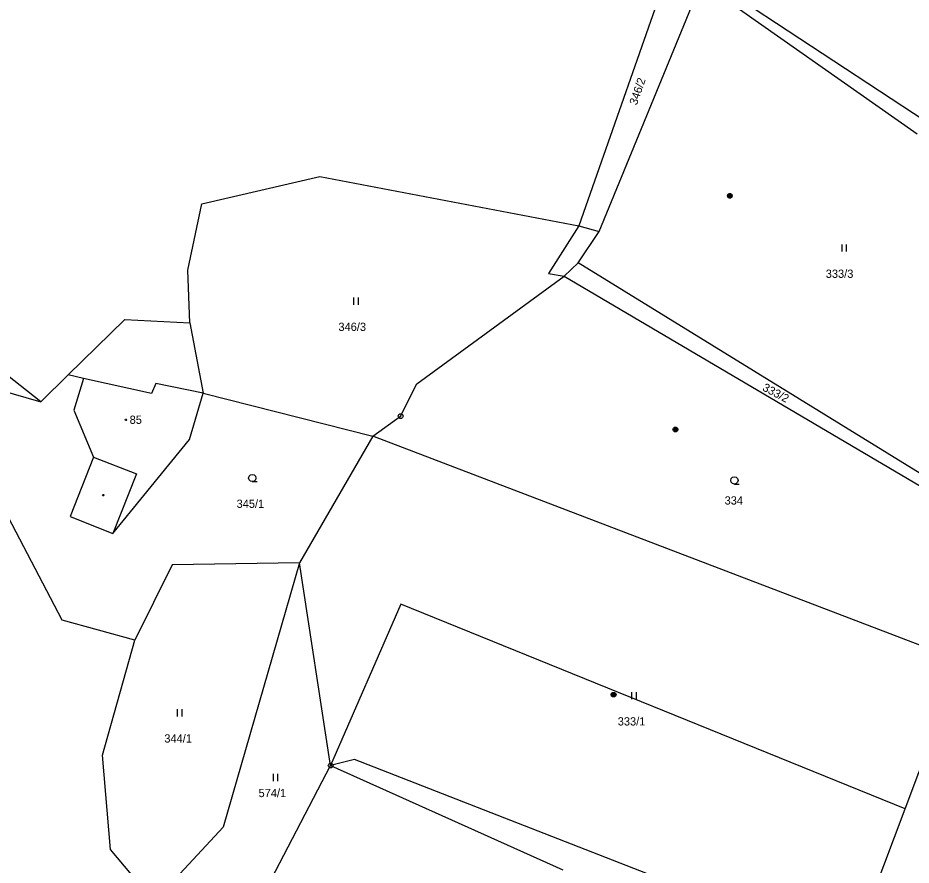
# Model space of a CAD drawing. Extents: x -694465 to -690527, y -983694 to -978978.
# Drawn here: x -692625.8 to -692441.8, y -981604.7 to -981430.2 of the extents above; entities that cross this region are included whole.
import ezdxf

# ---------------------------------------------------------------- set-up
doc = ezdxf.new("R2010")
doc.units = 0
for name, color, linetype in [('Vrstva 1', 7, 'Continuous'), ('Vrstva 18', 7, 'Continuous'), ('Vrstva 19', 7, 'Continuous'), ('Vrstva 24', 7, 'Continuous'), ('Vrstva 25', 7, 'Continuous'), ('Vrstva 26', 7, 'Continuous')]:
    doc.layers.add(name, color=color, linetype=linetype)

msp = doc.modelspace()

# ---------------------------------------------------------------- linework, layer by layer
at = {"layer": 'Vrstva 1'}
for points in [[(-692490.44, -981416.36), (-692510.29, -981472.97)], [(-692506.12, -981474.15), (-692485.04, -981422.83)], [(-692485.04, -981422.83), (-692440.58, -981454.06)], [(-692438.95, -981451.45), (-692476.57, -981426.72)], [(-692587.95, -981468.48), (-692563.64, -981462.84)], [(-692563.64, -981462.84), (-692510.29, -981472.97)], [(-692590.86, -981482.14), (-692587.95, -981468.48)], [(-692621.12, -981509.23), (-692665.4, -981474.33)], [(-692510.29, -981472.97), (-692516.53, -981482.79)], [(-692510.4, -981480.6), (-692506.12, -981474.15)], [(-692510.29, -981472.97), (-692506.12, -981474.15)], [(-692510.4, -981480.6), (-692513.28, -981483.34)], [(-692428.7, -981530.97), (-692510.4, -981480.6)], [(-692590.43, -981492.99), (-692590.86, -981482.14)], [(-692543.67, -981505.54), (-692513.28, -981483.34)], [(-692516.53, -981482.79), (-692513.28, -981483.34)], [(-692513.28, -981483.34), (-692428.36, -981533.41)], [(-692615.475, -981503.709), (-692603.78, -981492.27)], [(-692603.78, -981492.27), (-692590.43, -981492.99)], [(-692590.43, -981492.99), (-692587.69, -981507.45)], [(-692621.12, -981509.23), (-692615.475, -981503.709)], [(-692612.35, -981504.49), (-692615.475, -981503.709)], [(-692635.66, -981505.07), (-692621.12, -981509.23)], [(-692612.35, -981504.49), (-692614.34, -981511)], [(-692598.29, -981507.58), (-692612.35, -981504.49)], [(-692597.42, -981505.47), (-692598.29, -981507.58)], [(-692587.69, -981507.45), (-692597.42, -981505.47)], [(-692546.99, -981512.2), (-692543.67, -981505.54)], [(-692590.47, -981517.03), (-692587.69, -981507.45)], [(-692587.69, -981507.45), (-692552.71, -981516.36)], [(-692614.34, -981511), (-692610.29, -981520.64)], [(-692616.72, -981554.28), (-692638.99, -981511.81)], [(-692552.71, -981516.36), (-692546.99, -981512.2)], [(-692552.71, -981516.36), (-692567.81, -981542.46)], [(-692431.57, -981562.6), (-692552.71, -981516.36)], [(-692606.26, -981536.37), (-692590.47, -981517.03)], [(-692610.29, -981520.64), (-692615.1, -981532.9)], [(-692610.29, -981520.64), (-692601.44, -981524.11)], [(-692601.44, -981524.11), (-692606.26, -981536.37)], [(-692615.1, -981532.9), (-692606.26, -981536.37)], [(-692567.81, -981542.46), (-692594.07, -981542.83)], [(-692567.81, -981542.46), (-692583.58, -981596.88)], [(-692561.41, -981584.19), (-692567.81, -981542.46)], [(-692594.07, -981542.83), (-692601.73, -981558.39)], [(-692443.06, -981593.114), (-692546.953, -981550.948), (-692561.41, -981584.19)], [(-692601.73, -981558.39), (-692616.72, -981554.28)], [(-692608.43, -981582.04), (-692601.73, -981558.39)], [(-692443.06, -981593.114), (-692431.57, -981562.6)], [(-692606.77, -981601.48), (-692608.43, -981582.04)], [(-692556.51, -981582.94), (-692561.41, -981584.19)], [(-692454.26, -981622.86), (-692556.51, -981582.94)], [(-692582.39, -981624.43), (-692561.41, -981584.19)], [(-692561.41, -981584.19), (-692513.61, -981605.72)], [(-692454.26, -981622.86), (-692443.06, -981593.114)], [(-692583.58, -981596.88), (-692597.76, -981612.22)], [(-692597.76, -981612.22), (-692606.77, -981601.48)]]:
    msp.add_lwpolyline(points, dxfattribs=at)
at = {"layer": 'Vrstva 24'}
for points in [[(-692546.836, -981511.724), (-692546.586, -981511.906), (-692546.49, -981512.2), (-692546.586, -981512.494), (-692546.836, -981512.676), (-692547.144, -981512.676), (-692547.394, -981512.494), (-692547.49, -981512.2), (-692547.394, -981511.906), (-692547.144, -981511.724)], [(-692561.256, -981583.714), (-692561.006, -981583.896), (-692560.91, -981584.19), (-692561.006, -981584.484), (-692561.256, -981584.666), (-692561.564, -981584.666), (-692561.814, -981584.484), (-692561.91, -981584.19), (-692561.814, -981583.896), (-692561.564, -981583.714)], [(-692561.256, -981583.714), (-692561.006, -981583.896), (-692560.91, -981584.19), (-692561.006, -981584.484), (-692561.256, -981584.666), (-692561.564, -981584.666), (-692561.814, -981584.484), (-692561.91, -981584.19), (-692561.814, -981583.896), (-692561.564, -981583.714)]]:
    msp.add_lwpolyline(points, close=True, dxfattribs=at)
for points in [[(-692547.109, -981512.2), (-692546.87, -981512.2)], [(-692561.529, -981584.19), (-692561.29, -981584.19)], [(-692561.529, -981584.19), (-692561.29, -981584.19)]]:
    msp.add_lwpolyline(points, dxfattribs=at)
at = {"layer": 'Vrstva 25'}
for points in [[(-692456.13, -981476.82), (-692456.13, -981478.32)], [(-692455.13, -981478.32), (-692455.13, -981476.82)], [(-692556.7, -981487.76), (-692556.7, -981489.26)], [(-692555.7, -981489.26), (-692555.7, -981487.76)], [(-692577.57, -981525.71), (-692577.945, -981525.609), (-692578.219, -981525.335), (-692578.32, -981524.96), (-692578.219, -981524.585), (-692577.945, -981524.311), (-692577.57, -981524.21), (-692577.195, -981524.311), (-692576.921, -981524.585), (-692576.82, -981524.96), (-692576.921, -981525.335), (-692577.195, -981525.609), (-692577.57, -981525.71), (-692576.57, -981525.711)], [(-692478.22, -981526.21), (-692478.595, -981526.109), (-692478.869, -981525.835), (-692478.97, -981525.46), (-692478.869, -981525.085), (-692478.595, -981524.811), (-692478.22, -981524.71), (-692477.845, -981524.811), (-692477.571, -981525.085), (-692477.47, -981525.46), (-692477.571, -981525.835), (-692477.845, -981526.109), (-692478.22, -981526.21), (-692477.22, -981526.211)], [(-692499.42, -981569.05), (-692499.42, -981570.55)], [(-692498.42, -981570.55), (-692498.42, -981569.05)], [(-692593, -981572.57), (-692593, -981574.07)], [(-692592, -981574.07), (-692592, -981572.57)], [(-692573.26, -981585.9), (-692573.26, -981587.4)], [(-692572.26, -981587.4), (-692572.26, -981585.9)]]:
    msp.add_lwpolyline(points, dxfattribs=at)
for points in [[(-692603.513, -981512.828), (-692603.425, -981512.98), (-692603.513, -981513.132), (-692603.687, -981513.132), (-692603.775, -981512.98), (-692603.687, -981512.828)], [(-692608.183, -981528.348), (-692608.095, -981528.5), (-692608.183, -981528.652), (-692608.357, -981528.652), (-692608.445, -981528.5), (-692608.357, -981528.348)]]:
    msp.add_lwpolyline(points, close=True, dxfattribs=at)
at = {"layer": 'Vrstva 26'}
for points in [[(-692479.335, -981466.334), (-692479.025, -981466.334), (-692478.775, -981466.516), (-692478.68, -981466.81), (-692478.775, -981467.104), (-692479.025, -981467.286), (-692479.335, -981467.286), (-692479.585, -981467.104), (-692479.68, -981466.81), (-692479.585, -981466.516), (-692479.335, -981466.334), (-692479.3, -981466.37), (-692479.06, -981466.37), (-692478.9, -981466.45), (-692479.46, -981466.45), (-692479.54, -981466.53), (-692478.82, -981466.53), (-692478.82, -981466.61), (-692479.54, -981466.61), (-692479.582, -981466.69), (-692478.78, -981466.691), (-692478.74, -981466.77), (-692479.62, -981466.77), (-692479.62, -981466.85), (-692478.74, -981466.85), (-692478.771, -981466.929), (-692479.585, -981466.929), (-692479.579, -981467.01), (-692478.771, -981467.01), (-692478.82, -981467.09), (-692479.54, -981467.09), (-692479.46, -981467.17), (-692478.9, -981467.17), (-692479.008, -981467.249), (-692479.348, -981467.249)], [(-692490.545, -981514.494), (-692490.235, -981514.494), (-692489.985, -981514.676), (-692489.89, -981514.97), (-692489.985, -981515.264), (-692490.235, -981515.446), (-692490.545, -981515.446), (-692490.795, -981515.264), (-692490.89, -981514.97), (-692490.795, -981514.676), (-692490.545, -981514.494), (-692490.51, -981514.53), (-692490.27, -981514.53), (-692490.11, -981514.61), (-692490.67, -981514.61), (-692490.75, -981514.69), (-692490.03, -981514.69), (-692490.03, -981514.77), (-692490.75, -981514.77), (-692490.792, -981514.85), (-692489.99, -981514.851), (-692489.95, -981514.93), (-692490.83, -981514.93), (-692490.83, -981515.01), (-692489.95, -981515.01), (-692489.981, -981515.089), (-692490.795, -981515.089), (-692490.789, -981515.17), (-692489.981, -981515.17), (-692490.03, -981515.25), (-692490.75, -981515.25), (-692490.67, -981515.33), (-692490.11, -981515.33), (-692490.218, -981515.409), (-692490.558, -981515.409)], [(-692503.275, -981569.124), (-692502.965, -981569.124), (-692502.715, -981569.306), (-692502.62, -981569.6), (-692502.715, -981569.894), (-692502.965, -981570.076), (-692503.275, -981570.076), (-692503.525, -981569.894), (-692503.62, -981569.6), (-692503.525, -981569.306), (-692503.275, -981569.124), (-692503.24, -981569.16), (-692503, -981569.16), (-692502.84, -981569.24), (-692503.4, -981569.24), (-692503.48, -981569.32), (-692502.76, -981569.32), (-692502.76, -981569.4), (-692503.48, -981569.4), (-692503.522, -981569.48), (-692502.72, -981569.481), (-692502.68, -981569.56), (-692503.56, -981569.56), (-692503.56, -981569.64), (-692502.68, -981569.64), (-692502.711, -981569.719), (-692503.525, -981569.719), (-692503.519, -981569.8), (-692502.711, -981569.8), (-692502.76, -981569.88), (-692503.48, -981569.88), (-692503.4, -981569.96), (-692502.84, -981569.96), (-692502.948, -981570.039), (-692503.288, -981570.039)]]:
    msp.add_lwpolyline(points, dxfattribs=at)

# ---------------------------------------------------------------- texts
at = {"layer": 'Vrstva 18'}
for s, rotation, p in [('346/2', 71.10406, (-692498.324, -981448.24)), ('333/2', 332.08634, (-692472.59, -981506.836))]:
    msp.add_text(s, height=1.7, rotation=rotation, dxfattribs=at).set_placement(p)
for s, p in [('333/3', (-692459.411, -981483.72)), ('346/3', (-692559.807, -981494.66)), ('345/1', (-692580.789, -981531.11)), ('334', (-692480.248, -981530.43)), ('333/1', (-692502.266, -981575.95)), ('344/1', (-692595.672, -981579.47)), ('574/1', (-692576.263, -981590.71))]:
    msp.add_text(s, height=1.7, dxfattribs=at).set_placement(p)
at = {"layer": 'Vrstva 19'}
msp.add_text('85', height=1.7, dxfattribs=at).set_placement((-692602.819, -981513.8))

doc.saveas('drawing.dxf')
